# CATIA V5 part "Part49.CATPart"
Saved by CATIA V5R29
Part number: Main Alu inclosure
Revision: ANY
Definition: UNKNOWN
Nomenclature: Main Alu inclosure
Source: Unknown
Bounding box of the stored display mesh (mm): x -20 to 20, y -20 to 20, z 0 to 71.5
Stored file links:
  C:\Users\Administrator\Desktop\프로젝트\Gripper\Part49.CATPart
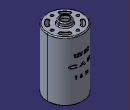
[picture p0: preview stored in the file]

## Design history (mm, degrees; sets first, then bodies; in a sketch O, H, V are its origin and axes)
Body1 "Fillet2" (main body)
  Solid1: solid without history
